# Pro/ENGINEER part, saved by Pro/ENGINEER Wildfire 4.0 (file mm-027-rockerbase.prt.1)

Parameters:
  METRIC = "NO"

Other parameters: PITCH, DRILL_DIAMETER, THREAD_DIAMETER, THREADS_PER_INCH, DRILL_POINT_ANGLE, DRILL_DEPTH, THREAD_DEPTH, THREAD_LENGTH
